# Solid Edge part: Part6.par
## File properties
Author: CADCIM
Template: Normal.par
Last saved by: CADCIM
Revision: 4
Application: Solid Edge
Accuracy: 0.99
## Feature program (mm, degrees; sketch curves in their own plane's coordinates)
body "unnamed Body 1"
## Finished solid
Body 1: solid body, 43 faces, 102 edges, 68 vertices.
  Faces by surface: cylinder 28, plane 15
  Edges by curve: circle 56, line 46
Bounding box of the edges (mm): 1353.852 x 457.200 x 1295.400, from (-676.9261, -203.2, -533.4) to (676.9261, 254, 762).
Cylindrical faces by radius (mm): R50.8 x6, R95.25 x6, R127 x5, R152.4 x2, R254 x2, R431.8 x2, R508 x2, R533.4 x3
Planar faces by outward normal: +x 1, +y 7, -x 1, -y 2, oblique 4
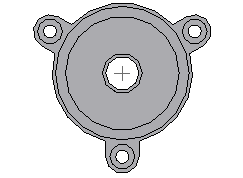
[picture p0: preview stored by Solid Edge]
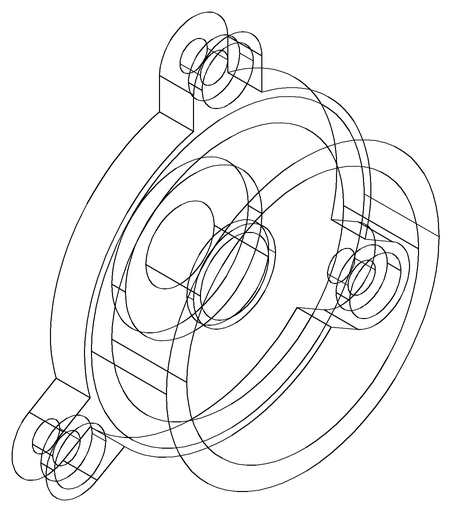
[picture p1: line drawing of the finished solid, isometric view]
